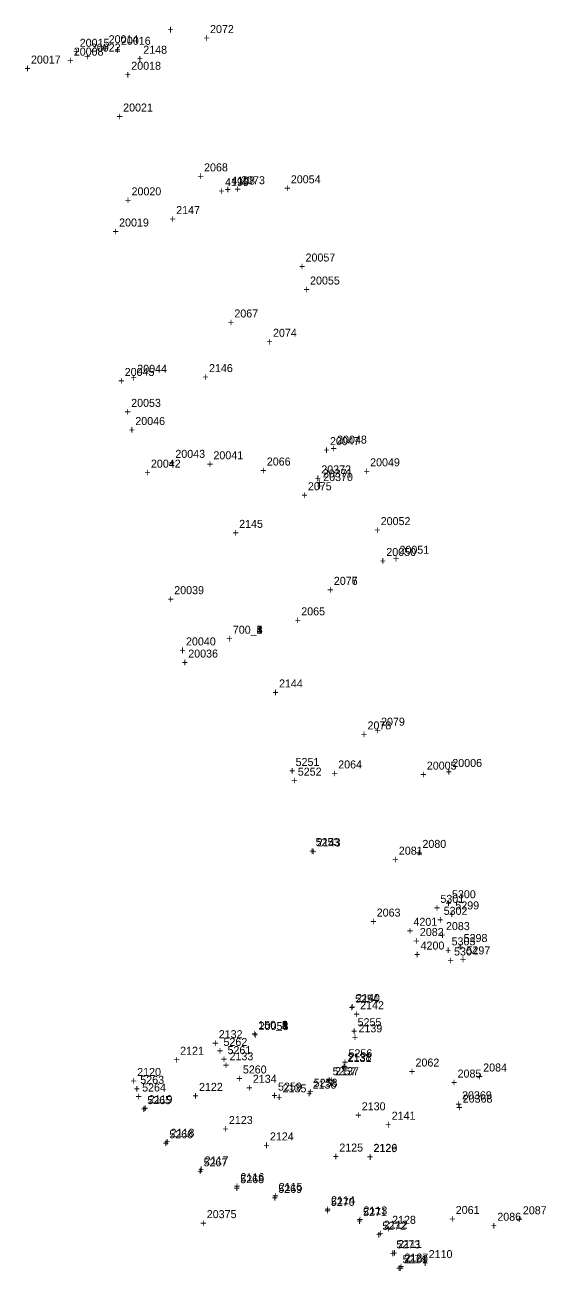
# Model space of a CAD drawing. Extents: x 1036751 to 1042192, y 772604 to 785439.
# Drawn here: x 1041606.1 to 1041769.1, y 773422.6 to 773812 of the extents above; entities that cross this region are included whole.
import ezdxf

# ---------------------------------------------------------------- set-up
doc = ezdxf.new("R2010")
doc.units = 0
for name, color, linetype in [('S_Buildings', 7, 'Continuous'), ('S_Buildings_SillElevation', 7, 'Continuous'), ('S_Control_Temp_Traverse', 7, 'Continuous'), ('S_Curb_Type_1', 7, 'Continuous'), ('S_Curb_Type_3', 7, 'Continuous'), ('S_Fencing_Picket', 7, 'Continuous'), ('S_Ground_LevelString', 7, 'Continuous'), ('S_Property_IronPipeFound', 7, 'Continuous'), ('S_Property_StoneWall', 7, 'Continuous'), ('S_Roadway_Centerline', 7, 'Continuous'), ('S_Roadway_Edge_Pavement', 7, 'Continuous'), ('S_Roadway_Edge_TW', 7, 'Continuous'), ('S_Trees_Decid_Pay', 7, 'Continuous'), ('S_Utilities_GuyWire3', 7, 'Continuous'), ('S_Utilities_Hydrant', 7, 'Continuous'), ('S_Utilities_Pole_Power', 7, 'Continuous'), ('S_Utilities_UG_Sanitary_MH', 7, 'Continuous'), ('S_Utilities_UG_Sanitary_Sewer', 7, 'Continuous'), ('S_Utilities_UG_Water_Line', 7, 'Continuous')]:
    doc.layers.add(name, color=color, linetype=linetype)

msp = doc.modelspace()

# ---------------------------------------------------------------- texts
at = {"layer": 'S_Buildings'}
for s, p in [('20054', (1041689.27, 773762.55)), ('+', (1041687.21, 773759.8)), ('+', (1041693.23, 773728.17)), ('20055', (1041695.29, 773730.92)), ('20045', (1041637.31, 773702.35)), ('+', (1041639.16, 773700.59)), ('20044', (1041641.22, 773703.34)), ('+', (1041635.25, 773699.6)), ('20046', (1041640.63, 773687.01)), ('+', (1041638.57, 773684.26)), ('20049', (1041714.08, 773674.11)), ('+', (1041712.02, 773671.36)), ('20050', (1041719.15, 773646.09)), ('20051', (1041723.26, 773646.79)), ('+', (1041717.09, 773643.34)), ('+', (1041721.2, 773644.04)), ('20039', (1041652.8, 773634.16)), ('+', (1041650.74, 773631.41)), ('20036', (1041657.19, 773614.35)), ('+', (1041655.13, 773611.6))]:
    msp.add_text(s, height=2.5, dxfattribs=at).set_placement(p)
at = {"layer": 'S_Buildings_SillElevation'}
for s, p in [('20057', (1041693.88, 773738.11)), ('+', (1041691.82, 773735.36)), ('20053', (1041639.33, 773692.69)), ('+', (1041637.27, 773689.94)), ('20052', (1041717.39, 773655.74)), ('+', (1041715.33, 773652.99)), ('+', (1041654.42, 773615.4)), ('20040', (1041656.48, 773618.15))]:
    msp.add_text(s, height=2.5, dxfattribs=at).set_placement(p)
at = {"layer": 'S_Control_Temp_Traverse'}
for s, p in [('+', (1041669.07, 773619.05)), ('+', (1041669.07, 773619.05)), ('+', (1041669.07, 773619.05)), ('+', (1041669.07, 773619.05)), ('+', (1041669.07, 773619.05)), ('+', (1041669.07, 773619.05)), ('+', (1041669.07, 773619.05)), ('700', (1041671.13, 773621.8)), ('700', (1041671.13, 773621.8)), ('700_5', (1041671.13, 773621.8)), ('700_4', (1041671.13, 773621.8)), ('700_3', (1041671.13, 773621.8)), ('700_2', (1041671.13, 773621.8)), ('700_1', (1041671.13, 773621.8)), ('150', (1041679.06, 773498.33)), ('150', (1041679.06, 773498.33)), ('150_1', (1041679.06, 773498.33)), ('150_3', (1041679.06, 773498.33)), ('150_2', (1041679.06, 773498.33)), ('150_5', (1041679.06, 773498.33)), ('150_4', (1041679.06, 773498.33)), ('+', (1041677, 773495.58)), ('+', (1041677, 773495.58)), ('+', (1041677, 773495.58)), ('+', (1041677, 773495.58)), ('+', (1041677, 773495.58)), ('+', (1041677, 773495.58)), ('+', (1041677, 773495.58))]:
    msp.add_text(s, height=2.5, dxfattribs=at).set_placement(p)
at = {"layer": 'S_Curb_Type_1'}
for s, p in [('5251', (1041690.77, 773580.48)), ('+', (1041688.71, 773577.73)), ('5252', (1041691.45, 773577.45)), ('+', (1041689.39, 773574.7)), ('+', (1041694.97, 773552.68)), ('5253', (1041697.03, 773555.43)), ('5301', (1041736.06, 773537.7)), ('+', (1041734, 773534.95)), ('5302', (1041737.09, 773533.96)), ('+', (1041735.03, 773531.21)), ('+', (1041737.5, 773521.66)), ('5303', (1041739.56, 773524.41)), ('5304', (1041740.33, 773521.26)), ('+', (1041738.27, 773518.51)), ('5254', (1041709.36, 773506.5)), ('+', (1041707.3, 773503.75)), ('5255', (1041710.16, 773499.15)), ('+', (1041708.1, 773496.4)), ('+', (1041666.13, 773490.24)), ('5262', (1041668.2, 773492.99)), ('5261', (1041669.47, 773490.42)), ('+', (1041667.41, 773487.67)), ('+', (1041705.24, 773486.7)), ('5256', (1041707.3, 773489.45)), ('5260', (1041674.26, 773484.38)), ('5257', (1041702.35, 773483.81)), ('+', (1041672.2, 773481.63)), ('5259', (1041685.26, 773479.03)), ('5258', (1041696.43, 773480.23)), ('+', (1041700.29, 773481.06)), ('+', (1041683.2, 773476.28)), ('+', (1041694.37, 773477.48))]:
    msp.add_text(s, height=2.5, dxfattribs=at).set_placement(p)
at = {"layer": 'S_Curb_Type_3'}
for s, p in [('5300', (1041739.68, 773539.13)), ('+', (1041737.62, 773536.38)), ('5299', (1041740.73, 773535.66)), ('+', (1041738.67, 773532.91)), ('5298', (1041743.33, 773525.46)), ('+', (1041741.27, 773522.71)), ('5297', (1041744.22, 773521.59)), ('+', (1041742.15, 773518.84)), ('5263', (1041642.18, 773481.15)), ('5264', (1041642.76, 773478.75)), ('+', (1041640.12, 773478.4)), ('+', (1041640.7, 773476)), ('5265', (1041644.38, 773474.8)), ('+', (1041642.32, 773472.05)), ('5266', (1041651.26, 773464.13)), ('+', (1041649.2, 773461.38)), ('5267', (1041661.98, 773455.37)), ('+', (1041659.92, 773452.62)), ('+', (1041671.39, 773447.36)), ('5268', (1041673.45, 773450.11)), ('5269', (1041685.35, 773447.07)), ('+', (1041683.29, 773444.32)), ('5270', (1041701.81, 773443.01)), ('+', (1041699.75, 773440.26)), ('5271', (1041711.84, 773439.82)), ('+', (1041709.78, 773437.07)), ('5272', (1041717.9, 773435.54)), ('+', (1041715.83, 773432.79)), ('5273', (1041722.27, 773429.72)), ('+', (1041720.21, 773426.97)), ('5274', (1041724.24, 773425.07)), ('+', (1041722.18, 773422.32))]:
    msp.add_text(s, height=2.5, dxfattribs=at).set_placement(p)
at = {"layer": 'S_Fencing_Picket'}
for s, p in [('20015', (1041623.23, 773805.2)), ('20014', (1041632.29, 773806.32)), ('+', (1041621.17, 773802.45)), ('+', (1041630.23, 773803.57))]:
    msp.add_text(s, height=2.5, dxfattribs=at).set_placement(p)
at = {"layer": 'S_Ground_LevelString'}
for s, p in [('2131', (1041707.06, 773487.98)), ('+', (1041705, 773485.23)), ('2130', (1041711.47, 773472.88)), ('+', (1041709.41, 773470.13)), ('2129', (1041715.16, 773459.81)), ('+', (1041713.1, 773457.06)), ('2128', (1041720.96, 773437.4)), ('+', (1041718.9, 773434.65)), ('2127', (1041724.82, 773425.61)), ('+', (1041722.76, 773422.86))]:
    msp.add_text(s, height=2.5, dxfattribs=at).set_placement(p)
at = {"layer": 'S_Property_IronPipeFound'}
for s, p in [('20008', (1041621.38, 773802.44)), ('+', (1041619.32, 773799.69))]:
    msp.add_text(s, height=2.5, dxfattribs=at).set_placement(p)
at = {"layer": 'S_Property_StoneWall'}
for s, p in [('20016', (1041636.13, 773805.83)), ('+', (1041634.07, 773803.08)), ('20017', (1041607.98, 773799.96)), ('+', (1041605.92, 773797.21))]:
    msp.add_text(s, height=2.5, dxfattribs=at).set_placement(p)
at = {"layer": 'S_Roadway_Centerline'}
for s, p in [('+', (1041650.66, 773809.35)), ('2068', (1041662.13, 773766.28)), ('+', (1041660.07, 773763.53)), ('2067', (1041671.61, 773720.63)), ('+', (1041669.55, 773717.88)), ('2066', (1041681.76, 773674.35)), ('+', (1041679.7, 773671.6)), ('2065', (1041692.53, 773627.54)), ('+', (1041690.47, 773624.79)), ('2064', (1041704.09, 773579.7)), ('+', (1041702.03, 773576.95)), ('2063', (1041716.14, 773533.41)), ('+', (1041714.08, 773530.66)), ('2121', (1041654.64, 773490.23)), ('+', (1041652.58, 773487.48)), ('2062', (1041728.28, 773486.55)), ('+', (1041726.22, 773483.8)), ('2122', (1041660.55, 773478.94)), ('+', (1041658.49, 773476.19)), ('2123', (1041669.9, 773468.59)), ('+', (1041667.84, 773465.84)), ('2124', (1041682.74, 773463.47)), ('+', (1041680.67, 773460.72)), ('2125', (1041704.43, 773459.98)), ('2126', (1041715.11, 773459.89)), ('+', (1041702.37, 773457.23)), ('+', (1041713.05, 773457.14)), ('2061', (1041740.86, 773440.47)), ('+', (1041738.8, 773437.72))]:
    msp.add_text(s, height=2.5, dxfattribs=at).set_placement(p)
at = {"layer": 'S_Roadway_Edge_Pavement'}
for s, p in [('2072', (1041664.01, 773809.5)), ('+', (1041661.95, 773806.75)), ('2148', (1041643.11, 773803.03)), ('+', (1041641.05, 773800.28)), ('+', (1041671.67, 773759.51)), ('2073', (1041673.73, 773762.26)), ('2147', (1041653.42, 773752.93)), ('+', (1041651.36, 773750.18)), ('2074', (1041683.7, 773714.59)), ('+', (1041681.64, 773711.84)), ('+', (1041661.62, 773700.79)), ('2146', (1041663.68, 773703.54)), ('2075', (1041694.61, 773666.62)), ('+', (1041692.55, 773663.87)), ('2145', (1041673.11, 773654.88)), ('+', (1041671.05, 773652.14)), ('+', (1041700.66, 773634.3)), ('2076', (1041702.72, 773637.05)), ('2144', (1041685.57, 773605)), ('+', (1041683.51, 773602.25)), ('2079', (1041717.5, 773593.07)), ('+', (1041715.44, 773590.32)), ('+', (1041695.34, 773552.57)), ('2143', (1041697.4, 773555.32)), ('2080', (1041730.44, 773554.88)), ('+', (1041728.37, 773552.13)), ('2083', (1041737.8, 773529.18)), ('+', (1041735.74, 773526.43)), ('2140', (1041709.7, 773506.71)), ('+', (1041707.64, 773503.96)), ('2132', (1041666.73, 773495.41)), ('+', (1041708.38, 773494.49)), ('2139', (1041710.44, 773497.24)), ('+', (1041664.67, 773492.66)), ('2133', (1041670.1, 773488.51)), ('2138', (1041707.02, 773488.22)), ('2120', (1041641.22, 773483.6)), ('+', (1041668.04, 773485.76)), ('2137', (1041703.14, 773483.85)), ('+', (1041704.96, 773485.47)), ('2084', (1041749.44, 773485)), ('+', (1041639.16, 773480.85)), ('+', (1041675.33, 773478.71)), ('2134', (1041677.39, 773481.46)), ('2135', (1041686.7, 773478.49)), ('2136', (1041696.1, 773479.64)), ('+', (1041701.08, 773481.1)), ('+', (1041747.38, 773482.25)), ('2119', (1041644.79, 773475.09)), ('+', (1041684.64, 773475.74)), ('+', (1041694.04, 773476.89)), ('+', (1041642.73, 773472.34)), ('2118', (1041651.66, 773464.59)), ('+', (1041649.6, 773461.84)), ('2117', (1041662.31, 773455.97)), ('+', (1041660.25, 773453.22)), ('+', (1041671.48, 773447.98)), ('2116', (1041673.54, 773450.73)), ('2115', (1041685.48, 773447.69)), ('+', (1041683.42, 773444.94)), ('2114', (1041701.86, 773443.53)), ('+', (1041699.8, 773440.78)), ('2113', (1041712, 773440.31)), ('2087', (1041761.85, 773440.38)), ('+', (1041709.94, 773437.56)), ('2112', (1041718.38, 773435.88)), ('+', (1041759.79, 773437.63)), ('+', (1041716.31, 773433.13)), ('2111', (1041722.78, 773429.84)), ('+', (1041720.72, 773427.09)), ('2109', (1041724.74, 773425.09)), ('+', (1041722.68, 773422.34))]:
    msp.add_text(s, height=2.5, dxfattribs=at).set_placement(p)
at = {"layer": 'S_Roadway_Edge_TW'}
for s, p in [('+', (1041700.67, 773634.33)), ('2077', (1041702.73, 773637.08)), ('2078', (1041713.26, 773591.9)), ('+', (1041711.2, 773589.15)), ('2081', (1041723.06, 773552.76)), ('+', (1041721, 773550.01)), ('2082', (1041729.63, 773527.33)), ('+', (1041727.57, 773524.58)), ('2142', (1041710.95, 773504.47)), ('+', (1041708.89, 773501.72)), ('2085', (1041741.44, 773483.1)), ('+', (1041739.37, 773480.35)), ('+', (1041718.76, 773467.18)), ('2141', (1041720.82, 773469.93)), ('2086', (1041753.87, 773438.36)), ('+', (1041751.81, 773435.61)), ('2110', (1041732.39, 773426.68)), ('+', (1041730.33, 773423.93))]:
    msp.add_text(s, height=2.5, dxfattribs=at).set_placement(p)
at = {"layer": 'S_Trees_Decid_Pay'}
for s, p in [('20022', (1041626.71, 773803.69)), ('+', (1041624.65, 773800.94)), ('+', (1041634.76, 773782.23)), ('20021', (1041636.82, 773784.98)), ('20020', (1041639.45, 773758.78)), ('+', (1041637.39, 773756.03)), ('20019', (1041635.56, 773749.05)), ('+', (1041633.5, 773746.3)), ('20047', (1041701.52, 773680.73)), ('20048', (1041703.75, 773681.21)), ('20043', (1041653.15, 773676.76)), ('+', (1041699.46, 773677.98)), ('+', (1041701.69, 773678.46)), ('20042', (1041645.51, 773673.69)), ('+', (1041651.09, 773674.01)), ('+', (1041643.44, 773670.94)), ('20058', (1041679.22, 773497.95)), ('+', (1041677.16, 773495.2))]:
    msp.add_text(s, height=2.5, dxfattribs=at).set_placement(p)
at = {"layer": 'S_Utilities_GuyWire3'}
for s, p in [('20006', (1041739.79, 773580.17)), ('+', (1041737.73, 773577.42))]:
    msp.add_text(s, height=2.5, dxfattribs=at).set_placement(p)
at = {"layer": 'S_Utilities_Hydrant'}
for s, p in [('20375', (1041662.98, 773439.17)), ('+', (1041660.92, 773436.42))]:
    msp.add_text(s, height=2.5, dxfattribs=at).set_placement(p)
at = {"layer": 'S_Utilities_Pole_Power'}
for s, p in [('20018', (1041639.36, 773798.03)), ('+', (1041637.3, 773795.28)), ('+', (1041663, 773673.56)), ('20041', (1041665.06, 773676.31)), ('20005', (1041731.81, 773579.33)), ('+', (1041729.75, 773576.58))]:
    msp.add_text(s, height=2.5, dxfattribs=at).set_placement(p)
at = {"layer": 'S_Utilities_UG_Sanitary_MH'}
for s, p in [('20371', (1041699.26, 773670.65)), ('+', (1041697.2, 773667.9)), ('20368', (1041743.04, 773475.28)), ('+', (1041740.98, 773472.53))]:
    msp.add_text(s, height=2.5, dxfattribs=at).set_placement(p)
at = {"layer": 'S_Utilities_UG_Sanitary_Sewer'}
for s, p in [('20372', (1041698.8, 773671.9)), ('20370', (1041699.4, 773669.5)), ('+', (1041696.74, 773669.15)), ('+', (1041697.34, 773666.75)), ('4201', (1041727.62, 773530.52)), ('+', (1041725.56, 773527.77)), ('4200', (1041729.86, 773523.11)), ('+', (1041727.8, 773520.36)), ('20369', (1041742.83, 773476.32)), ('+', (1041740.77, 773473.57))]:
    msp.add_text(s, height=2.5, dxfattribs=at).set_placement(p)
at = {"layer": 'S_Utilities_UG_Water_Line'}
for s, p in [('+', (1041666.63, 773758.93)), ('+', (1041668.58, 773759.41)), ('4199', (1041668.7, 773761.68)), ('4198', (1041670.64, 773762.16))]:
    msp.add_text(s, height=2.5, dxfattribs=at).set_placement(p)

doc.saveas('drawing.dxf')
